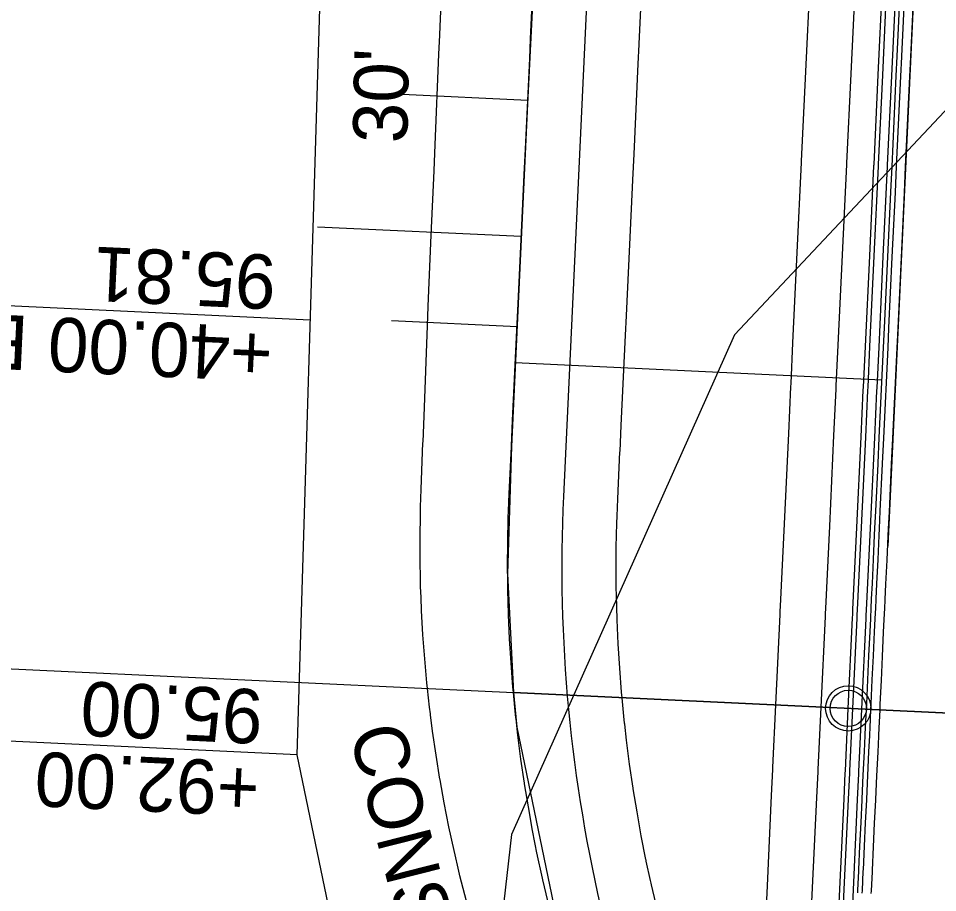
# Model space of a CAD drawing. Extents: x -70 to 701944, y -4 to 666871.
# Drawn here: x 668152.2 to 668253.6, y 654725.8 to 654822.3 of the extents above; entities that cross this region are included whole.
import ezdxf

# ---------------------------------------------------------------- set-up
doc = ezdxf.new("R2010")
doc.units = 0
for name, color, linetype in [('R_Detour', 7, 'Continuous'), ('R_Drive', 7, 'Continuous'), ('R_No Plot', 7, 'Continuous'), ('R_Proposed Const Limits', 7, 'Continuous'), ('R_Proposed Road', 7, 'Continuous'), ('R_ROW', 7, 'Continuous'), ('R_ROW Annot', 7, 'Continuous'), ('R_Temp Easement Annot', 7, 'Continuous'), ('R_Water', 7, 'Continuous'), ('T_Drafting', 7, 'Continuous'), ('T_Indications', 7, 'Continuous')]:
    doc.layers.add(name, color=color, linetype=linetype)

msp = doc.modelspace()

# ---------------------------------------------------------------- linework, layer by layer
at = {"layer": 'R_Detour'}
msp.add_line((668132.02, 654751.44), (668278.19, 654744.54), dxfattribs=at)
at = {"layer": 'R_Drive'}
for p, q in [((668185.18, 654799.34), (668207.65, 654798.28)), ((668247.45, 654782.39), (668206.99, 654784.3))]:
    msp.add_line(p, q, dxfattribs=at)
at = {"layer": 'R_No Plot'}
for p, q in [((668215.9, 654845.79), (668212.3, 654769.57)), ((668208.36, 654813.27), (668194.51, 654813.92)), ((668207.18, 654788.29), (668193.33, 654788.95))]:
    msp.add_line(p, q, dxfattribs=at)
for points in [[(668210.9, 654857.84), (668210.34, 654852.46), (668208.34, 654812.91), (668206.56, 654775.07), (668206.14, 654761), (668206.78, 654747.91), (668278.19, 654744.54), (668283.38, 654854.41)], [(668278.19, 654744.54), (668206.78, 654747.91), (668207.17, 654744.1), (668217.4, 654694.69), (668218.98, 654682.6), (668219.54, 654657.72), (668214.33, 654547.33), (668268.77, 654544.76)]]:
    msp.add_lwpolyline(points, close=True, dxfattribs=at)
msp.add_circle((668243.73, 654746.16), 2.5, dxfattribs=at)
msp.add_arc((668378.12, 654761.74), 166, 177.2978, 193.5476, dxfattribs=at)
at = {"layer": 'R_Proposed Const Limits'}
msp.add_lwpolyline([(668203.42, 654718.03), (668200.89, 654727.67), (668200.84, 654727.86), (668200.77, 654728.17), (668200.27, 654730.31), (668200.25, 654730.4), (668200.23, 654730.47), (668199.67, 654733.09), (668199.15, 654735.72), (668198.69, 654738.28), (668198.67, 654738.36), (668198.25, 654741), (668197.87, 654743.65), (668197.63, 654745.44), (668197.62, 654745.55), (668197.53, 654746.31), (668197.3, 654748.35), (668197.24, 654748.97), (668197, 654751.63), (668196.8, 654754.29), (668196.65, 654756.96), (668196.59, 654758.4), (668196.55, 654759.63), (668196.53, 654760.51), (668196.52, 654760.62), (668196.49, 654762.3), (668196.48, 654764.97), (668196.52, 654767.64), (668196.54, 654768.41), (668196.6, 654770.31), (668196.8, 654775.53), (668196.81, 654775.6), (668196.92, 654778.41), (668197.3, 654788.4), (668197.39, 654790.54), (668197.39, 654790.57), (668197.71, 654798.39), (668198.03, 654805.52), (668198.04, 654805.56), (668198.16, 654808.38), (668198.57, 654818.37), (668198.66, 654820.5), (668198.67, 654820.55), (668199, 654828.36)], dxfattribs=at)
at = {"layer": 'R_Proposed Road'}
msp.add_line((668252.26, 654852.63), (668248.08, 654764.08), dxfattribs=at)
for points in [[(668212.32, 654717.61), (668210.02, 654727.24), (668209.98, 654727.43), (668209.91, 654727.74), (668209.45, 654729.87), (668209.44, 654729.96), (668209.42, 654730.04), (668208.9, 654732.66), (668208.43, 654735.28), (668208.01, 654737.84), (668208, 654737.92), (668207.62, 654740.56), (668207.28, 654743.21), (668207.07, 654744.99), (668207.06, 654745.1), (668206.98, 654745.86), (668206.78, 654747.91), (668206.73, 654748.52), (668206.52, 654751.18), (668206.36, 654753.84), (668206.24, 654756.51), (668206.19, 654757.95), (668206.16, 654759.18), (668206.15, 654760.05), (668206.15, 654760.16), (668206.13, 654761.85), (668206.15, 654764.52), (668206.21, 654767.19), (668206.23, 654767.96), (668206.31, 654769.85), (668206.56, 654775.07), (668206.56, 654775.14), (668206.69, 654777.95), (668207.16, 654787.93), (668207.26, 654790.08), (668207.27, 654790.1), (668207.63, 654797.92), (668207.97, 654805.05), (668207.97, 654805.09), (668208.11, 654807.91), (668208.58, 654817.9), (668208.68, 654820.03), (668208.68, 654820.08), (668209.05, 654827.89)], [(668224.31, 654717.05), (668222.01, 654726.67), (668221.97, 654726.86), (668221.9, 654727.17), (668221.44, 654729.31), (668221.42, 654729.4), (668221.41, 654729.47), (668220.89, 654732.09), (668220.42, 654734.72), (668220, 654737.27), (668219.99, 654737.35), (668219.6, 654740), (668219.26, 654742.64), (668219.06, 654744.43), (668219.05, 654744.54), (668218.97, 654745.3), (668218.77, 654747.34), (668218.71, 654747.95), (668218.51, 654750.61), (668218.34, 654753.28), (668218.22, 654755.94), (668218.18, 654757.38), (668218.15, 654758.61), (668218.13, 654759.49), (668218.13, 654759.6), (668218.12, 654761.28), (668218.13, 654763.95), (668218.19, 654766.62), (668218.22, 654767.39), (668218.3, 654769.29), (668218.54, 654774.5), (668218.55, 654774.57), (668218.68, 654777.38), (668219.15, 654787.37), (668219.25, 654789.51), (668219.25, 654789.53), (668219.62, 654797.36), (668219.96, 654804.49), (668219.96, 654804.53), (668220.09, 654807.35), (668220.56, 654817.33), (668220.66, 654819.46), (668220.67, 654819.51), (668221.04, 654827.32)], [(668244.77, 654725.79), (668244.79, 654726.09), (668244.89, 654728.2), (668244.89, 654728.29), (668244.9, 654728.36), (668245.02, 654730.95), (668245.14, 654733.55), (668245.26, 654736.08), (668245.26, 654736.16), (668245.39, 654738.78), (668245.51, 654741.4), (668245.6, 654743.17), (668245.6, 654743.28), (668245.64, 654744.04), (668245.73, 654746.07), (668245.76, 654746.68), (668245.89, 654749.32), (668246.01, 654751.97), (668246.14, 654754.63), (668246.2, 654756.06), (668246.26, 654757.29), (668246.3, 654758.16), (668246.31, 654758.27), (668246.39, 654759.95), (668246.51, 654762.61), (668246.64, 654765.28), (668246.67, 654766.05), (668246.76, 654767.94), (668247.01, 654773.16), (668247.01, 654773.23), (668247.15, 654776.04), (668247.62, 654786.02), (668247.72, 654788.17), (668247.72, 654788.19), (668248.09, 654796.01), (668248.43, 654803.14), (668248.43, 654803.18), (668248.56, 654806), (668249.03, 654815.99), (668249.13, 654818.12), (668249.14, 654818.17), (668249.5, 654825.98)], [(668245.27, 654725.76), (668245.29, 654726.07), (668245.39, 654728.18), (668245.39, 654728.27), (668245.4, 654728.34), (668245.52, 654730.93), (668245.64, 654733.53), (668245.76, 654736.06), (668245.76, 654736.14), (668245.89, 654738.75), (668246.01, 654741.38), (668246.09, 654743.15), (668246.1, 654743.26), (668246.14, 654744.01), (668246.23, 654746.05), (668246.26, 654746.65), (668246.38, 654749.3), (668246.51, 654751.95), (668246.64, 654754.6), (668246.7, 654756.03), (668246.76, 654757.26), (668246.8, 654758.13), (668246.81, 654758.24), (668246.89, 654759.92), (668247.01, 654762.59), (668247.14, 654765.25), (668247.17, 654766.02), (668247.26, 654767.92), (668247.51, 654773.14), (668247.51, 654773.21), (668247.65, 654776.01), (668248.12, 654786), (668248.22, 654788.14), (668248.22, 654788.17), (668248.59, 654795.99), (668248.93, 654803.12), (668248.93, 654803.16), (668249.06, 654805.98), (668249.53, 654815.97), (668249.63, 654818.1), (668249.63, 654818.15), (668250, 654825.96)], [(668246.27, 654725.72), (668246.29, 654726.02), (668246.39, 654728.13), (668246.39, 654728.22), (668246.39, 654728.29), (668246.52, 654730.88), (668246.64, 654733.48), (668246.76, 654736.01), (668246.76, 654736.09), (668246.89, 654738.71), (668247.01, 654741.33), (668247.09, 654743.1), (668247.1, 654743.21), (668247.13, 654743.97), (668247.23, 654746), (668247.26, 654746.61), (668247.38, 654749.25), (668247.51, 654751.9), (668247.63, 654754.56), (668247.7, 654755.99), (668247.76, 654757.22), (668247.8, 654758.09), (668247.81, 654758.19), (668247.89, 654759.88), (668248.01, 654762.54), (668248.14, 654765.21), (668248.17, 654765.98), (668248.26, 654767.87), (668248.51, 654773.09), (668248.51, 654773.16), (668248.64, 654775.97), (668249.12, 654785.95), (668249.22, 654788.1), (668249.22, 654788.12), (668249.59, 654795.94), (668249.92, 654803.07), (668249.93, 654803.11), (668250.06, 654805.93), (668250.53, 654815.92), (668250.63, 654818.05), (668250.63, 654818.1), (668251, 654825.91)]]:
    msp.add_lwpolyline(points, dxfattribs=at)
at = {"layer": 'R_ROW'}
msp.add_lwpolyline([(668327.66, 653586.02), (668340.87, 653592.64), (668322.47, 653689.42), (668277.13, 653821.63), (668258.71, 653853.34), (668224.55, 653854.19), (668177.85, 653978.14), (668204.74, 653982.28), (668180.35, 654097), (668169.32, 654193.98), (668198.41, 654666.21), (668182.92, 654741.02), (668186.49, 654858.99), (668209, 654933.01), (668212.48, 655027.95)], dxfattribs=at)
at = {"layer": 'R_ROW Annot'}
msp.add_lwpolyline([(668184.37, 654789.01), (668149.41, 654790.66)], dxfattribs=at)
at = {"layer": 'R_Temp Easement Annot'}
msp.add_lwpolyline([(668182.92, 654741.02), (668147.96, 654742.67)], dxfattribs=at)
at = {"layer": 'R_Water'}
msp.add_circle((668243.73, 654746.16), 2, dxfattribs=at)
at = {"layer": 'T_Drafting'}
msp.add_lwpolyline([(668523.3, 654913.99), (668505.08, 654903.26), (668442.36, 654901.65), (668353.91, 654883.95), (668302.45, 654860.35), (668281.55, 654841.04), (668231.16, 654787.41), (668206.57, 654732.23), (668203.35, 654703.8), (668186.2, 654694.15), (668142.25, 654696.83), (668095.61, 654705.41), (668080.6, 654700.05), (668074.7, 654674.3), (668078.99, 654639.98), (668057.7, 654627.18)], dxfattribs=at)
at = {"layer": 'T_Indications'}
for points in [[(668234.58, 654721.91), (668234.8, 654726.56), (668235.27, 654736.55), (668235.41, 654739.4), (668235.42, 654739.65), (668235.74, 654746.54), (668236.21, 654756.53), (668236.23, 654756.89), (668236.26, 654757.44), (668236.68, 654766.52), (668237.16, 654776.51), (668237.4, 654781.66), (668237.42, 654782.01), (668237.63, 654786.5), (668238.1, 654796.48), (668238.57, 654806.43), (668238.57, 654806.47), (668238.58, 654806.59), (668239.04, 654816.46), (668239.51, 654826.45)], [(668239.57, 654721.68), (668239.79, 654726.33), (668240.26, 654736.32), (668240.4, 654739.17), (668240.41, 654739.41), (668240.74, 654746.3), (668241.21, 654756.29), (668241.22, 654756.65), (668241.25, 654757.2), (668241.68, 654766.28), (668242.15, 654776.27), (668242.39, 654781.42), (668242.41, 654781.78), (668242.62, 654786.26), (668243.09, 654796.25), (668243.56, 654806.19), (668243.56, 654806.24), (668243.57, 654806.35), (668244.04, 654816.23), (668244.51, 654826.22)], [(668242.57, 654721.54), (668242.79, 654726.19), (668243.26, 654736.17), (668243.4, 654739.02), (668243.41, 654739.27), (668243.73, 654746.16), (668244.2, 654756.15), (668244.22, 654756.51), (668244.25, 654757.06), (668244.68, 654766.14), (668245.15, 654776.13), (668245.39, 654781.28), (668245.41, 654781.63), (668245.62, 654786.12), (668246.09, 654796.11), (668246.56, 654806.05), (668246.56, 654806.1), (668246.57, 654806.21), (668247.03, 654816.09), (668247.5, 654826.07)], [(668243.07, 654721.51), (668243.29, 654726.16), (668243.76, 654736.15), (668243.9, 654739), (668243.91, 654739.25), (668244.23, 654746.14), (668244.7, 654756.13), (668244.72, 654756.49), (668244.75, 654757.03), (668245.18, 654766.12), (668245.65, 654776.11), (668245.89, 654781.26), (668245.91, 654781.61), (668246.12, 654786.1), (668246.59, 654796.08), (668247.06, 654806.03), (668247.06, 654806.07), (668247.07, 654806.19), (668247.53, 654816.06), (668248, 654826.05)], [(668244.07, 654721.47), (668244.29, 654726.11), (668244.76, 654736.1), (668244.89, 654738.95), (668244.91, 654739.2), (668245.23, 654746.09), (668245.7, 654756.08), (668245.72, 654756.44), (668245.75, 654756.99), (668246.17, 654766.07), (668246.65, 654776.06), (668246.89, 654781.21), (668246.91, 654781.56), (668247.12, 654786.05), (668247.59, 654796.04), (668248.06, 654805.98), (668248.06, 654806.03), (668248.07, 654806.14), (668248.53, 654816.01), (668249, 654826)]]:
    msp.add_lwpolyline(points, dxfattribs=at)

# ---------------------------------------------------------------- texts
at = {"layer": 'R_Drive'}
msp.add_text("30'", height=6, rotation=89.0317, dxfattribs=at).set_placement((668195.07, 654808.52))
at = {"layer": 'R_Proposed Const Limits'}
msp.add_text('CONST. LIMITS', height=6, rotation=284.2216, dxfattribs=at).set_placement((668188.65, 654743.61))
at = {"layer": 'R_ROW Annot'}
for s, p in [('95.81', (668180.71, 654796.19)), ('+40.00 END C/A', (668180.33, 654788.2))]:
    msp.add_text(s, height=6, rotation=177.2978, dxfattribs=at).set_placement(p)
at = {"layer": 'R_Temp Easement Annot'}
for s, p in [('95.00', (668179.26, 654748.21)), ('+92.00', (668178.88, 654740.21))]:
    msp.add_text(s, height=6, rotation=177.2978, dxfattribs=at).set_placement(p)

doc.saveas('drawing.dxf')
